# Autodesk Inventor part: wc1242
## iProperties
Shininess: 64.0
Length Units: 11272
Angle Units: 11279
Time Units: 11290
Mass Units: 11286
Length Display Precision: 3
Angle Display Precision: 2
Compacted: True
Part Number: wc1242
Document SubType Name: Modeling
Created: 2004-08
Designer: John Blackburn
Manufacturer: Standard
Standards Organization: Custom
Material: Lexan, Clear
Density: 0.0
Volumn: 0.0
Area: 0.0
PropertySet Name: Model Information
Control State: 0
Master: False
Checked Out: False
Author: John Blackburn
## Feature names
1. Base1
